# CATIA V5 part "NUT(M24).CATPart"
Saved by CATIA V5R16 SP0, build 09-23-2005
Part number: NUT(M24)
Source: bought
Bounding box of the stored display mesh (mm): x -24 to 24, y -23.981 to 23.981, z -8 to 9.6
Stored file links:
  C:\V5_education\CATIA Data\ASD\Power Transmission Gear Assembly\Assembly Data\NUT(M24).CATPart
  C:\usr\gt1\projet\valve\doc\doc_2005\comp\M4.CATPart
  C:\usr\gt1\projet\valve\doc\doc_2005\cylinder1\hexagon.CATPart
  C:\Work\Workbench\KWA\CATPart\Gear\pump_kimm_2\pump_kimm_2\limiter\max_flow_block.CATProduct
  C:\Work\Workbench\KWA\CATPart\Gear\pump_kimm_2\pump_kimm_2\limiter\flow_nut.CATPart
  C:\V5_education\Assemble Design\CATProduct\Power Transmission Gear\Axis.CATPart
  C:\V5_education\CATIA Data\ASD\Power Transmission Gear Assembly\Assembly Data\Power Transmission Gear Assembly.CATProduct
  C:\V5_education\CATIA Data\ASD\Power Transmission Gear Assembly\Assembly Data\Power Transmission Gear.CATPart
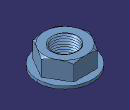
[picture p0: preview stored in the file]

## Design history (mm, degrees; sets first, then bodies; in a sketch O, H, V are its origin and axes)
External parameters (linked from other documents)
  External.M = 24 mm
  External.H = 36 mm
Set1
  DatumSurface1: linked copy from another document
Set2 "M24 Helix Body"
  Point1: (0, -12.2, -13), relative to Point2
  Line1: type PtDir, RefPoint Point2, Direction xy-plane, Start -20, End 25
  Helix1: Direction Line1, RefPoint Point1, Pitch 2, Height 25, TaperAngle 0
  Sweep1: type Segment, GuideCrv Helix1, Length1 2, Length2 0, Angle 60, DraftDirection xy-plane
  Sweep2: type Segment, GuideCrv Helix1, Length1 2, Length2 0, Angle 60, DraftDirection xy-plane
  Trim1: Trimmed (Sweep1; Sweep2)
Set3 "Reference Data"
  Point2 "Center Point": (0, 0, 0)
  Plane1: type Offset, RefPlane xy-plane, Offset -5
  Plane2: type Offset, RefPlane Plane1, Offset -3
Body1 (main body)
  Sketch1 on xy-plane, origin (0, 0, 0), H (0, 1, 0), V (-1, 0, 0)
    point P1 (0, 0)
    point P2 (18, -10.3923)
    point P3 (18, 10.3923)
    point P4 (0, 20.7846)
    point P5 (-18, 10.3923)
    point P6 (-18, -10.3923)
    point P7 (0, -20.7846)
    point P8 (18, 0)
    line L1 (18, -10.3923) -> (18, 10.3923)
    line L2 (18, 10.3923) -> (0, 20.7846)
    line L3 (0, 20.7846) -> (-18, 10.3923)
    line L4 (-18, 10.3923) -> (-18, -10.3923)
    line L5 (-18, -10.3923) -> (0, -20.7846)
    line L6 (0, -20.7846) -> (18, -10.3923)
    construction line L7 (0, 0) -> (18, 0)
    construction arc A1 centre (0, 0) radius 20.7846 from (18, -10.3923) to (0, -20.7846) ccw
    construction arc A2 centre (-18, -10.3923) radius 20.7846 from (-18, 10.3923) to (0, -20.7846) cw
    construction arc A3 centre (18, 10.3923) radius 20.7846 from (0, 20.7846) to (18, -10.3923) ccw
    point P9 (-18, -10.3923)
    point P10 (18, 10.3923)
    distance L1 L4 = 36 {= External.H}
    coincidence: P1 O, A1 P2, A1 P3, A1 P4, A1 P5, A1 P6, A1 P7, A2 P5, A2 P7, A2 P1, P9 P6, A3 P4, A3 P2, A3 P1, P10 P3
    horizontal: L7 H
    midpoint: P8 L1
  Sketch2 on yz-plane, origin (0, 0, 0), H (0, 1, 0), V (0, 0, 1)
    line L1 (-20.7846, 7.9923) -> (-18, 9.6)
    point P2 (-18, 9.6)
    line L2 (-18, 9.6) -> (-11.1763, 9.6)
    line L3 (-20.7846, -9.6) -> (-11.1763, -9.6)
    line L4 (-10.3763, 8.8) -> (-10.3763, -8.8)
    line L5 (-20.7846, 7.9923) -> (-20.7846, -9.6)
    line L6 (-11.1763, 9.6) -> (-10.3763, 8.8)
    point P3 (-11.1763, 9.6)
    point P4 (-10.3762, 8.8)
    line L7 (-11.1763, -9.6) -> (-10.3763, -8.8)
    point P5 (-11.1763, -9.6)
    point P6 (-10.3762, -8.8)
    angle L1 L2 = 30
    distance P2 V = 18 {= External.H/2}
    distance L4 V = 10.3763
    distance L2 L3 = 19.2 {= External.M * 4 / 5}
    distance L5 V = 20.7846 {= External.H / sqrt( 3 )}
    angle L2 L6 = 45
    length L6 H = 0.8 {= External.M/30}
    horizontal: L2 H, L3 H
    vertical: L4 V, L5 V
    symmetry: P3 P5 H, P4 P6 H
  Shaft1: profile Sketch2, axis Sketch2.V, angle 360
  Pocket1: profile Sketch1, direction (0, 0, -1), through (limit type 6), opposite side through (limit type 6), outer side
  AssyPrtSPLIT1: _MechModInactiveResultOUT result of AssyPrtSPLIT1, deactivated
  Body2
    Sketch3 on Plane2, origin (0, 0, -8), H (1, 0, 0), V (0, 1, 0)
      circle A1 centre (0, 0) radius 24
      radius A1 = 24
    Pad1: profile Sketch3, direction (0, 0, 1), length 2.5
  Assemble1: tool Body2
  Split1: SplitPlane Plane2
  Split2: SplitPlane Trim1
  AssyPrtSPLIT2: SplitPlane DatumSurface1, _MechModInactiveResultOUT result of AssyPrtSPLIT2, deactivated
